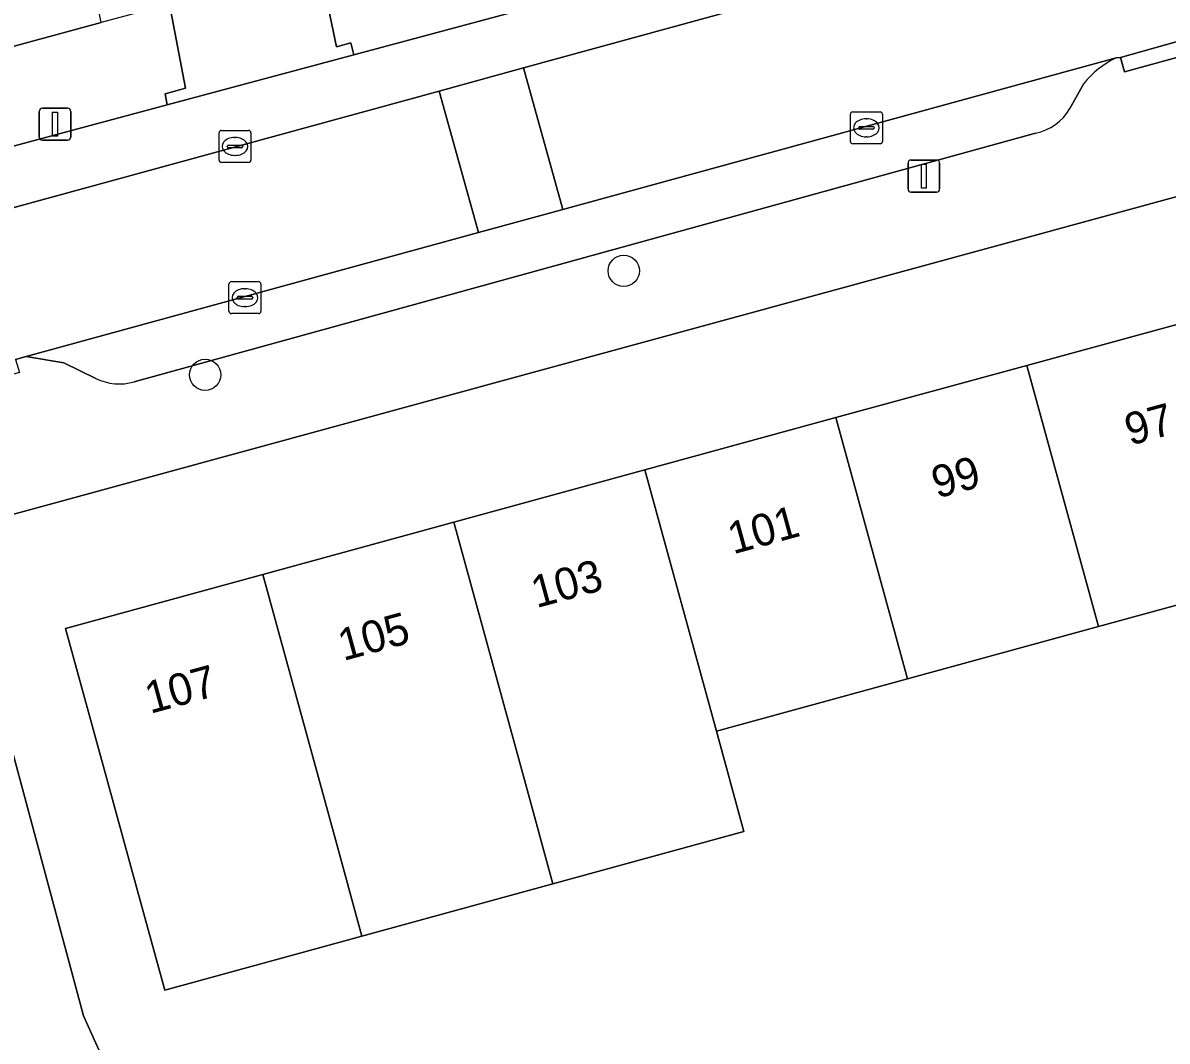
# Model space of a CAD drawing. Extents: x 163008 to 163854, y 382777 to 383982.
# Drawn here: x 163159.92 to 163195.74, y 383657.73 to 383689.61 of the extents above; entities that cross this region are included whole.
import ezdxf

# ---------------------------------------------------------------- set-up
doc = ezdxf.new("R2010")
doc.units = 0
for name, color, linetype in [('IMGEO_Boom', 7, 'Continuous'), ('IMGEO_Erf', 7, 'Continuous'), ('IMGEO_Kolk', 7, 'Continuous'), ('IMGEO_Lichtmast', 7, 'Continuous'), ('IMGEO_Pand', 7, 'Continuous'), ('IMGEO_Pand_nummerreeks', 7, 'Continuous'), ('IMGEO_Parkeervlak_open', 7, 'Continuous'), ('IMGEO_Rijbaan_lokaal_open', 7, 'Continuous'), ('IMGEO_Voetpad_open', 7, 'Continuous')]:
    doc.layers.add(name, color=color, linetype=linetype)

msp = doc.modelspace()

# ---------------------------------------------------------------- linework, layer by layer
at = {"layer": 'IMGEO_Boom'}
for centre in [(163178.727, 383681.842), (163165.621, 383678.588)]:
    msp.add_circle(centre, 0.489, dxfattribs=at)
at = {"layer": 'IMGEO_Erf'}
for points in [[(163135.878, 383682.415), (163162.366, 383689.615), (163161.624, 383693.273), (163147.11, 383690.257), (163146.529, 383692.887), (163143.036, 383692.148), (163140.153, 383691.539), (163139.953, 383692.465), (163139.483, 383692.807)], [(163196.514, 383684.3), (163157.902, 383673.76), (163157.928, 383673.599), (163157.761, 383673.548), (163161.815, 383658.517), (163167.561, 383645.782), (163172.328, 383647.292), (163174.18, 383647.878), (163175.016, 383644.78), (163177.382, 383645.538), (163177.904, 383643.906), (163178.645, 383644.143), (163181.34, 383645.006), (163180.958, 383646.153), (163186.707, 383648.069), (163186.868, 383647.585), (163192.711, 383649.533), (163192.137, 383651.346), (163198.048, 383653.316)], [(163196.956, 383671.627), (163193.591, 383670.706), (163187.611, 383669.07), (163181.631, 383667.434), (163182.492, 383664.291), (163176.511, 383662.654), (163170.53, 383661.018), (163164.356, 383659.326), (163163.504, 383662.43), (163162.575, 383665.827), (163161.255, 383670.649), (163167.43, 383672.339), (163173.411, 383673.975), (163179.392, 383675.612), (163185.372, 383677.248), (163191.352, 383678.884), (163197.531, 383680.575)]]:
    msp.add_lwpolyline(points, dxfattribs=at)
at = {"layer": 'IMGEO_Kolk'}
for p, q in [((163185.825, 383685.895), (163185.825, 383686.747)), ((163185.9, 383686.821), (163186.752, 383686.821)), ((163186.313, 383686.601), (163186.338, 383686.601)), ((163186.826, 383686.747), (163186.826, 383685.895)), ((163166.132, 383686.239), (163166.984, 383686.239)), ((163186.084, 383686.315), (163186.084, 383686.327)), ((163186.522, 383686.278), (163186.124, 383686.278)), ((163186.127, 383686.364), (163186.525, 383686.364)), ((163186.568, 383686.327), (163186.568, 383686.315)), ((163166.057, 383685.313), (163166.057, 383686.165)), ((163166.545, 383686.019), (163166.57, 383686.019)), ((163167.058, 383686.165), (163167.058, 383685.313)), ((163186.336, 383686.041), (163186.311, 383686.041)), ((163166.316, 383685.733), (163166.316, 383685.745)), ((163166.754, 383685.696), (163166.356, 383685.696)), ((163166.359, 383685.782), (163166.757, 383685.782)), ((163166.8, 383685.745), (163166.8, 383685.733)), ((163186.752, 383685.821), (163185.9, 383685.821)), ((163166.984, 383685.239), (163166.132, 383685.239)), ((163166.568, 383685.459), (163166.543, 383685.459)), ((163166.369, 383680.579), (163166.369, 383681.431)), ((163166.444, 383681.505), (163167.296, 383681.505)), ((163166.857, 383681.285), (163166.882, 383681.285)), ((163167.37, 383681.431), (163167.37, 383680.579)), ((163166.628, 383680.999), (163166.628, 383681.011)), ((163167.066, 383680.962), (163166.668, 383680.962)), ((163166.671, 383681.048), (163167.069, 383681.048)), ((163167.112, 383681.011), (163167.112, 383680.999)), ((163167.296, 383680.505), (163166.444, 383680.505)), ((163166.88, 383680.725), (163166.855, 383680.725))]:
    msp.add_line(p, q, dxfattribs=at)
for points in [[(163185.825, 383685.895), (163185.825, 383686.747)], [(163185.9, 383686.821), (163186.752, 383686.821)], [(163186.826, 383686.747), (163186.826, 383685.895)], [(163166.132, 383686.239), (163166.984, 383686.239)], [(163166.057, 383685.313), (163166.057, 383686.165)], [(163167.058, 383686.165), (163167.058, 383685.313)], [(163186.752, 383685.821), (163185.9, 383685.821)], [(163166.984, 383685.239), (163166.132, 383685.239)], [(163166.369, 383680.579), (163166.369, 383681.431)], [(163166.444, 383681.505), (163167.296, 383681.505)], [(163167.37, 383681.431), (163167.37, 383680.579)], [(163167.296, 383680.505), (163166.444, 383680.505)]]:
    msp.add_lwpolyline(points, dxfattribs=at)
for centre, radius, start, end in [((163185.902, 383686.745), 0.0765, 91.552, 178.448), ((163185.902, 383686.745), 0.0765, 91.552, 178.448), ((163186.75, 383686.745), 0.0765, 1.552, 88.448), ((163186.75, 383686.745), 0.0765, 1.552, 88.448), ((163166.134, 383686.163), 0.0765, 91.552, 178.448), ((163166.134, 383686.163), 0.0765, 91.552, 178.448), ((163166.982, 383686.163), 0.0765, 1.552, 88.448), ((163166.982, 383686.163), 0.0765, 1.552, 88.448), ((163186.124, 383686.324), 0.0403, 85.8775, 175.7526), ((163186.121, 383686.314), 0.0366, 178.938, 274.7102), ((163186.525, 383686.321), 0.043, 264.8664, 352.4533), ((163186.529, 383686.326), 0.0386, 1.7309, 96.639), ((163185.902, 383685.897), 0.0765, 181.552, 268.448), ((163185.902, 383685.897), 0.0765, 181.552, 268.448), ((163186.75, 383685.897), 0.0765, 271.552, 358.448), ((163186.75, 383685.897), 0.0765, 271.552, 358.448), ((163166.356, 383685.742), 0.0403, 85.8775, 175.7526), ((163166.353, 383685.732), 0.0366, 178.938, 274.7102), ((163166.757, 383685.739), 0.043, 264.8664, 352.4533), ((163166.761, 383685.744), 0.0386, 1.7309, 96.639), ((163166.134, 383685.315), 0.0765, 181.552, 268.448), ((163166.134, 383685.315), 0.0765, 181.552, 268.448), ((163166.982, 383685.315), 0.0765, 271.552, 358.448), ((163166.982, 383685.315), 0.0765, 271.552, 358.448), ((163166.446, 383681.429), 0.0765, 91.552, 178.448), ((163166.446, 383681.429), 0.0765, 91.552, 178.448), ((163167.294, 383681.429), 0.0765, 1.552, 88.448), ((163167.294, 383681.429), 0.0765, 1.552, 88.448), ((163166.668, 383681.008), 0.0403, 85.8775, 175.7526), ((163166.665, 383680.998), 0.0366, 178.938, 274.7102), ((163167.069, 383681.005), 0.043, 264.8664, 352.4533), ((163167.073, 383681.01), 0.0386, 1.7309, 96.639), ((163166.446, 383680.581), 0.0765, 181.552, 268.448), ((163166.446, 383680.581), 0.0765, 181.552, 268.448), ((163167.294, 383680.581), 0.0765, 271.552, 358.448), ((163167.294, 383680.581), 0.0765, 271.552, 358.448)]:
    msp.add_arc(centre, radius, start, end, dxfattribs=at)
for centre, major_axis, ratio, start_param, end_param in [((163186.312, 383686.321), (-0.387, 0.002), 0.722429, 4.712389, 7.853982), ((163186.337, 383686.321), (-0.39, 0.002), 0.717154, 1.570796, 4.712389), ((163166.544, 383685.739), (-0.387, 0.002), 0.722429, 4.712389, 7.853982), ((163166.569, 383685.739), (-0.39, 0.002), 0.717154, 1.570796, 4.712389), ((163166.856, 383681.005), (-0.387, 0.002), 0.722429, 4.712389, 7.853982), ((163166.881, 383681.005), (-0.39, 0.002), 0.717154, 1.570796, 4.712389)]:
    msp.add_ellipse(centre, major_axis=major_axis, ratio=ratio, start_param=start_param, end_param=end_param, dxfattribs=at)
at = {"layer": 'IMGEO_Lichtmast'}
for p, q in [((163160.428, 383686.033), (163160.428, 383686.833)), ((163160.428, 383686.833), (163160.428, 383686.033)), ((163160.528, 383686.933), (163161.318, 383686.933)), ((163161.318, 383686.933), (163160.528, 383686.933)), ((163161.418, 383686.833), (163161.418, 383686.033)), ((163161.418, 383686.033), (163161.418, 383686.833)), ((163161.318, 383685.933), (163160.528, 383685.933)), ((163160.528, 383685.933), (163161.318, 383685.933)), ((163187.628, 383684.412), (163187.628, 383685.212)), ((163187.628, 383685.212), (163187.628, 383684.412)), ((163187.728, 383685.312), (163188.518, 383685.312)), ((163188.518, 383685.312), (163187.728, 383685.312)), ((163188.618, 383685.212), (163188.618, 383684.412)), ((163188.618, 383684.412), (163188.618, 383685.212)), ((163188.518, 383684.312), (163187.728, 383684.312)), ((163187.728, 383684.312), (163188.518, 383684.312))]:
    msp.add_line(p, q, dxfattribs=at)
for points in [[(163160.848, 383686.808), (163160.998, 383686.808), (163160.998, 383686.058), (163160.848, 383686.058), (163160.848, 383686.808)], [(163188.048, 383685.187), (163188.198, 383685.187), (163188.198, 383684.437), (163188.048, 383684.437), (163188.048, 383685.187)]]:
    msp.add_lwpolyline(points, dxfattribs=at)
for centre, start, end in [((163160.528, 383686.833), 90, 180), ((163160.528, 383686.833), 90, 180), ((163161.318, 383686.833), 0, 90), ((163161.318, 383686.833), 360, 90), ((163160.528, 383686.033), 180, 270), ((163160.528, 383686.033), 180, 270), ((163161.318, 383686.033), 270, 0), ((163161.318, 383686.033), 270, 0), ((163187.728, 383685.212), 90, 180), ((163187.728, 383685.212), 90, 180), ((163188.518, 383685.212), 0, 90), ((163188.518, 383685.212), 360, 90), ((163187.728, 383684.412), 180, 270), ((163187.728, 383684.412), 180, 270), ((163188.518, 383684.412), 270, 0), ((163188.518, 383684.412), 270, 0)]:
    msp.add_arc(centre, 0.1, start, end, dxfattribs=at)
at = {"layer": 'IMGEO_Pand'}
for points in [[(163193.591, 383670.706), (163196.956, 383671.627), (163197.863, 383668.311), (163200.936, 383669.151), (163200.033, 383672.45), (163199.774, 383672.38), (163198.851, 383675.753), (163197.531, 383680.575), (163191.352, 383678.884)], [(163193.591, 383670.706), (163191.352, 383678.884), (163185.372, 383677.248), (163187.611, 383669.07)], [(163181.631, 383667.434), (163187.611, 383669.07), (163185.372, 383677.248), (163179.392, 383675.612)], [(163181.631, 383667.434), (163179.392, 383675.612), (163173.411, 383673.975), (163175.65, 383665.797), (163176.511, 383662.654), (163182.492, 383664.291)], [(163176.511, 383662.654), (163175.65, 383665.797), (163173.411, 383673.975), (163167.43, 383672.339), (163169.669, 383664.161), (163170.53, 383661.018)], [(163170.53, 383661.018), (163169.669, 383664.161), (163167.43, 383672.339), (163161.255, 383670.649), (163162.575, 383665.827), (163163.504, 383662.43), (163164.356, 383659.326)]]:
    msp.add_lwpolyline(points, close=True, dxfattribs=at)
at = {"layer": 'IMGEO_Parkeervlak_open'}
for points in [[(163238.122, 383707.13), (163191.332, 383694.26), (163170.273, 383688.608), (163164.434, 383687.041), (163140.525, 383680.624)], [(163137.21, 383677.691), (163172.951, 383687.473), (163175.593, 383688.197), (163241.241, 383706.164)], [(163194.145, 383688.516), (163176.819, 383683.765), (163174.179, 383683.04), (163160.021, 383679.158), (163161.198, 383678.96), (163162.2, 383678.475)], [(163192.695, 383686.928), (163193.128, 383687.714)], [(163163.406, 383678.371), (163191.614, 383686.156)]]:
    msp.add_lwpolyline(points, dxfattribs=at)
for centre, radius, start, end in [((163195.545, 383685.695), 3.149, 116.3904, 140.1278), ((163191.322, 383687.707), 1.579, 280.6503, 330.415), ((163162.936, 383679.961), 1.658, 243.6572, 286.4853)]:
    msp.add_arc(centre, radius, start, end, dxfattribs=at)
at = {"layer": 'IMGEO_Rijbaan_lokaal_open'}
for points in [[(163258.083, 383705.991), (163256.854, 383710.426), (163245.198, 383707.244), (163241.498, 383706.234), (163241.388, 383706.204), (163241.241, 383706.164), (163175.593, 383688.197), (163176.819, 383683.765), (163194.145, 383688.516), (163194.281, 383688.521), (163198.095, 383689.598), (163216.973, 383694.775), (163223.562, 383696.582)], [(163175.593, 383688.197), (163172.951, 383687.473), (163174.179, 383683.04), (163176.819, 383683.765)]]:
    msp.add_lwpolyline(points, close=True, dxfattribs=at)
for points in [[(163159.689, 383679.067), (163160.021, 383679.158), (163174.179, 383683.04), (163172.951, 383687.473), (163137.21, 383677.691)], [(163164.768, 383640.049), (163166.676, 383637.295), (163170.792, 383638.638), (163167.561, 383645.782), (163161.815, 383658.517), (163157.761, 383673.548), (163153.268, 383672.296), (163153.823, 383669.608), (163154.631, 383665.551), (163156.064, 383656.685), (163155.521, 383656.535), (163156.023, 383654.109), (163159.537, 383654.808), (163159.783, 383654.93), (163164.253, 383645.18)]]:
    msp.add_lwpolyline(points, dxfattribs=at)
at = {"layer": 'IMGEO_Voetpad_open'}
for points in [[(163346.588, 383743.249), (163340.162, 383739.998), (163333.582, 383736.669), (163333.018, 383737.783), (163316.721, 383732.415), (163315.71, 383732.082), (163316.054, 383731.008), (163308.39, 383728.558), (163300.723, 383726.106), (163298.053, 383725.418), (163290.312, 383723.243), (163282.57, 383721.068), (163282.25, 383722.208), (163268.944, 383718.534), (163269.048, 383718.072), (163261.121, 383716.284), (163242.045, 383711.035), (163225.973, 383706.902), (163169.191, 383691.469), (163169.732, 383688.86), (163170.179, 383688.982), (163170.273, 383688.608), (163191.332, 383694.26), (163238.122, 383707.13)], [(163135.19, 383672.222), (163136.465, 383666.013), (163138.679, 383666.445), (163137.681, 383671.283), (163137.963, 383671.408), (163152.793, 383674.52), (163153.268, 383672.296), (163157.761, 383673.548), (163157.928, 383673.599), (163157.902, 383673.76), (163196.514, 383684.3), (163198.675, 383684.89), (163249.86, 383698.862), (163250.659, 383699.08), (163310.588, 383715.439), (163310.002, 383718.169), (163310.732, 383720.107), (163312.031, 383720.54), (163311.95, 383720.858), (163318.877, 383722.615), (163325.662, 383724.337), (163332.588, 383726.094)], [(163164.434, 383687.041), (163164.372, 383687.384), (163165.007, 383687.558), (163164.505, 383690.196), (163162.366, 383689.615), (163135.878, 383682.415)], [(163198.095, 383689.598), (163198.217, 383689.113), (163194.405, 383688.069), (163194.281, 383688.521), (163194.145, 383688.516)], [(163193.128, 383687.714), (163192.695, 383686.928)], [(163140.525, 383680.624), (163164.434, 383687.041)], [(163191.614, 383686.156), (163163.406, 383678.371)], [(163162.2, 383678.475), (163161.198, 383678.96), (163160.021, 383679.158), (163159.689, 383679.067), (163159.813, 383678.664), (163138.735, 383672.851), (163138.625, 383673.279), (163136.148, 383672.62)]]:
    msp.add_lwpolyline(points, dxfattribs=at)
for points in [[(163169.191, 383691.469), (163164.505, 383690.196), (163165.007, 383687.558), (163164.372, 383687.384), (163164.434, 383687.041), (163170.273, 383688.608), (163170.179, 383688.982), (163169.732, 383688.86)], [(163194.281, 383688.521), (163194.405, 383688.069), (163198.217, 383689.113), (163198.095, 383689.598)]]:
    msp.add_lwpolyline(points, close=True, dxfattribs=at)
for centre, radius, start, end in [((163195.545, 383685.695), 3.149, 116.3904, 140.1278), ((163191.322, 383687.707), 1.579, 280.6503, 330.415), ((163162.936, 383679.961), 1.658, 243.6572, 286.4853)]:
    msp.add_arc(centre, radius, start, end, dxfattribs=at)

# ---------------------------------------------------------------- texts
at = {"layer": 'IMGEO_Pand_nummerreeks'}
for s, p in [('97', (163194.577, 383676.367)), ('99', (163188.531, 383674.712)), ('101', (163182.15, 383672.966)), ('103', (163175.994, 383671.281)), ('105', (163169.948, 383669.626)), ('107', (163163.902, 383667.972))]:
    msp.add_text(s, height=1, rotation=15.303, dxfattribs=at).set_placement(p)

doc.saveas('drawing.dxf')
